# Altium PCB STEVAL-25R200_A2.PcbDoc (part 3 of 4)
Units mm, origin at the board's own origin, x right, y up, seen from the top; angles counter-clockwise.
Board outline 84.5 x 100 mm, 4 copper layers (Top Layer, F2, F3, Bottom Layer), stack 0.78 mm thick; 272 components, 152 nets, 679 pads, 380 vias.
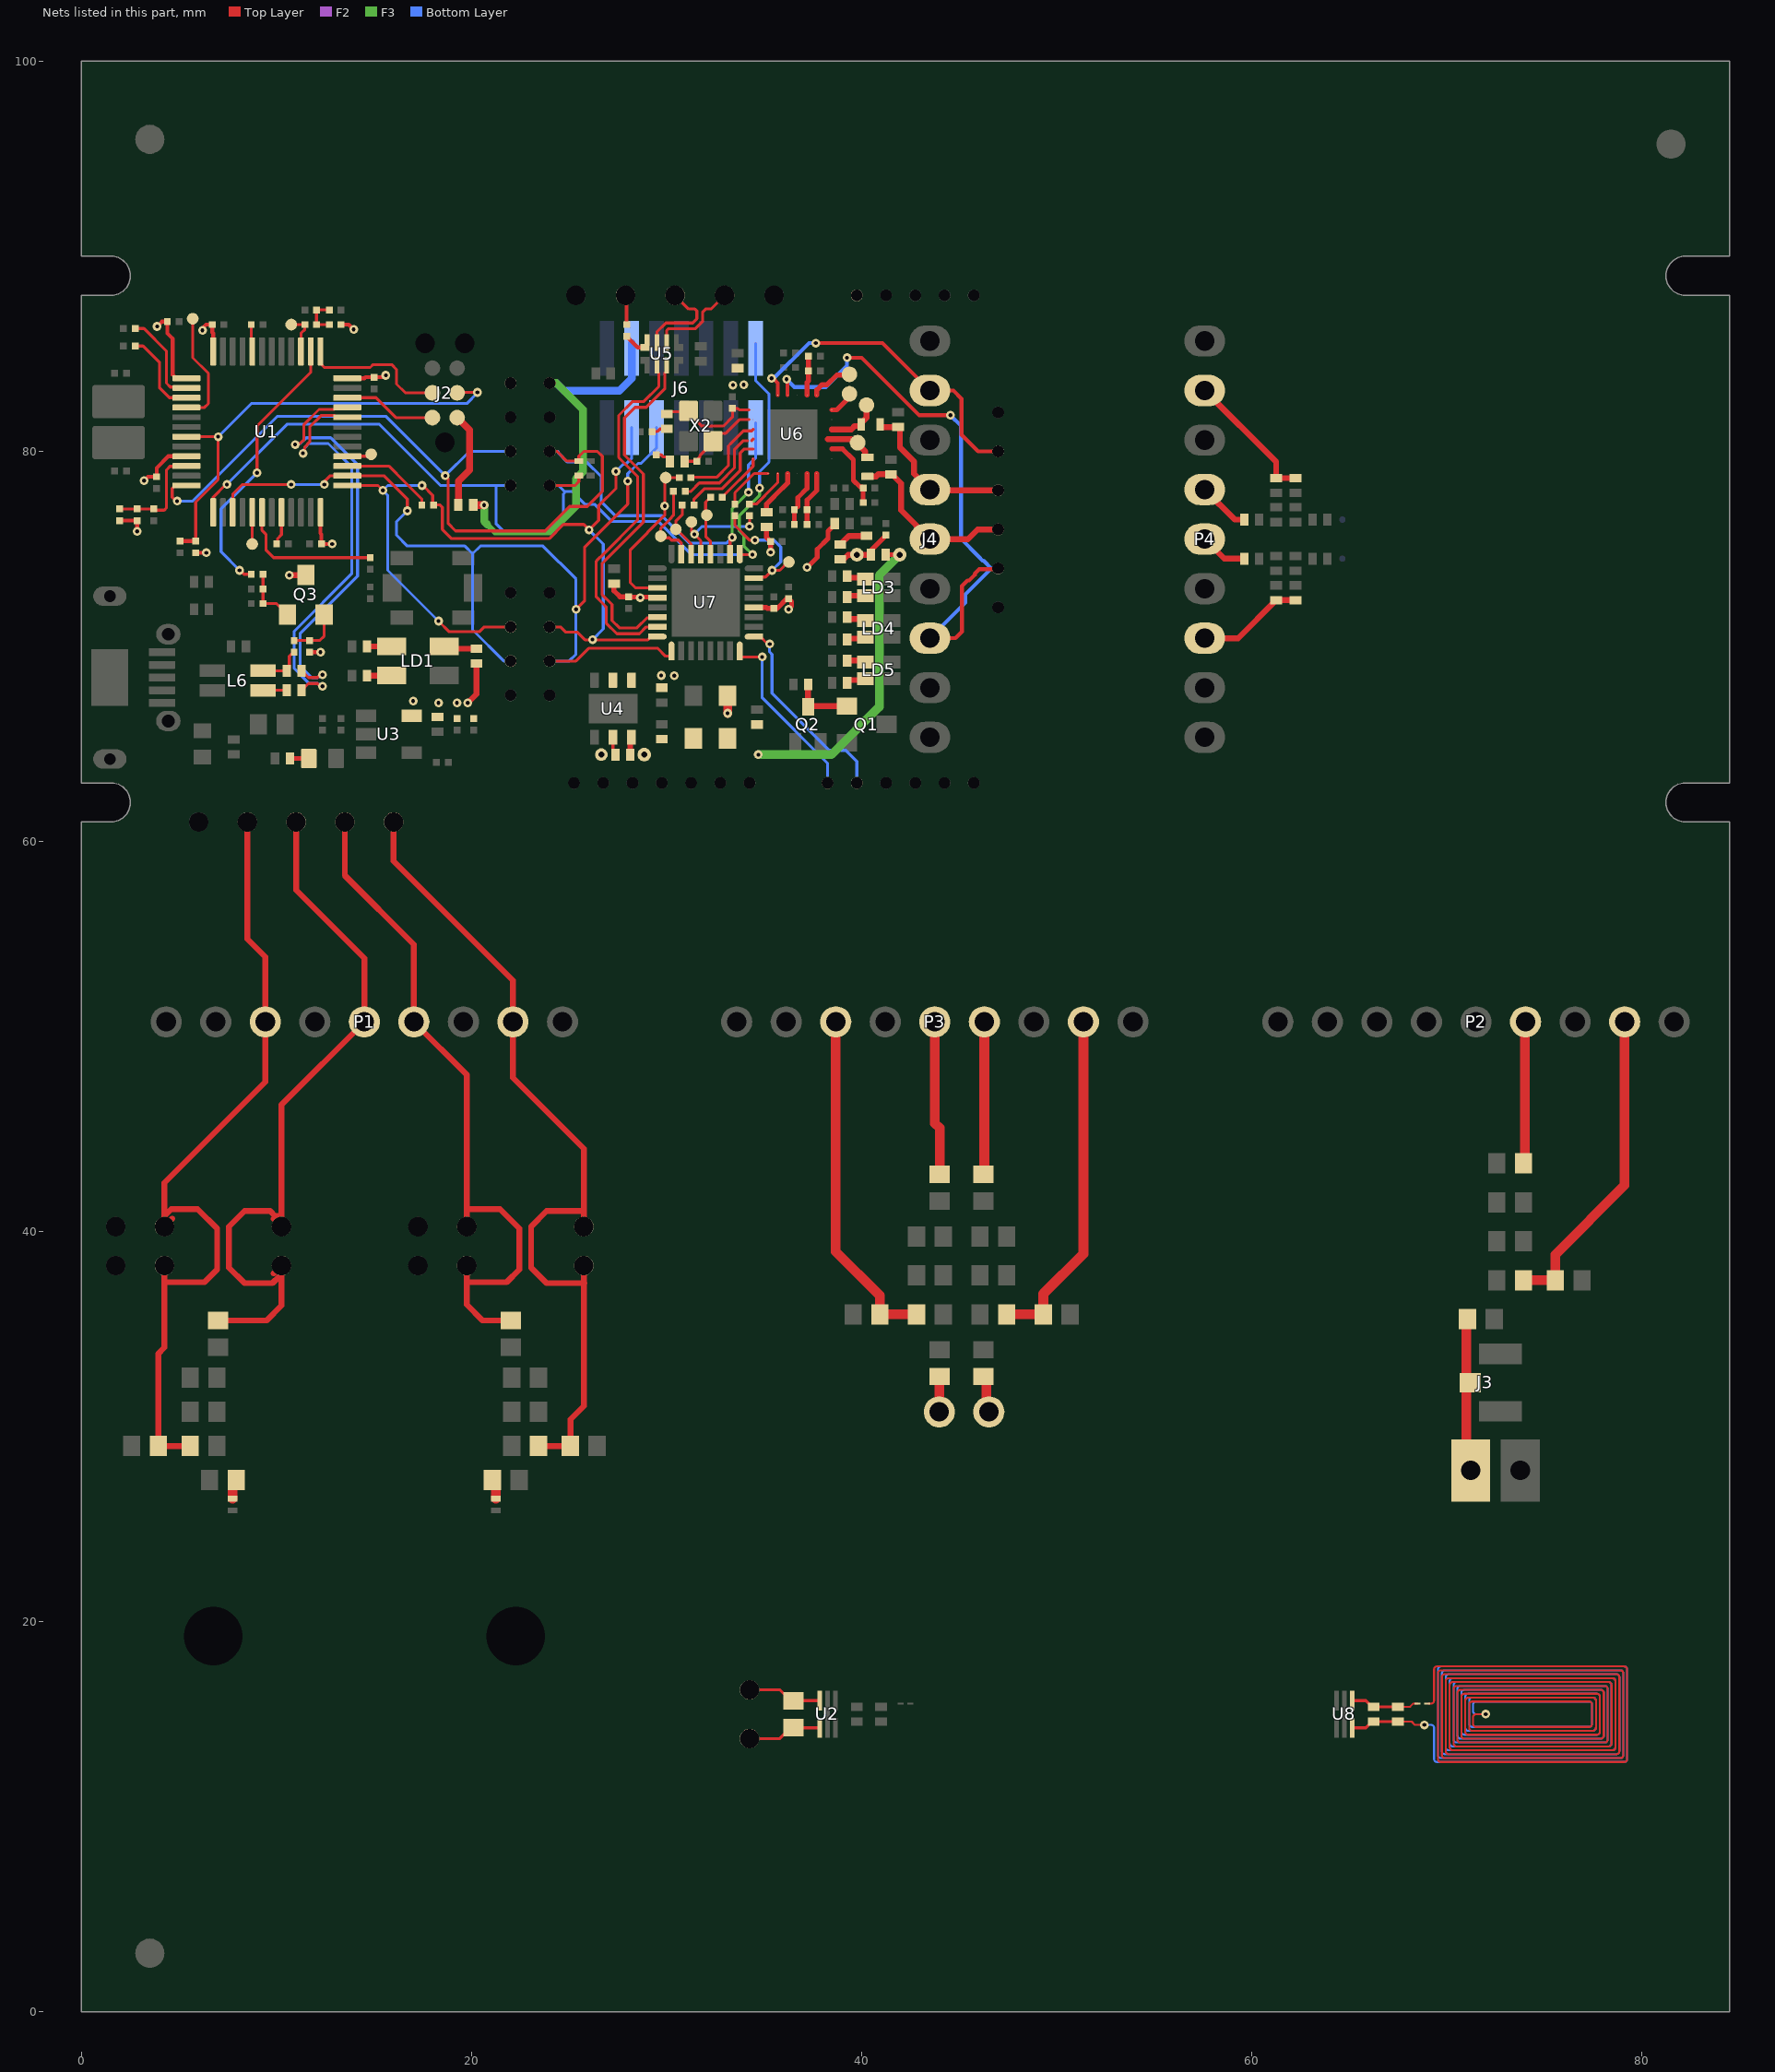
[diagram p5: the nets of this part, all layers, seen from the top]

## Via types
v1: diameter 0.45, hole 0.2, Top Layer to Bottom Layer, 380 vias

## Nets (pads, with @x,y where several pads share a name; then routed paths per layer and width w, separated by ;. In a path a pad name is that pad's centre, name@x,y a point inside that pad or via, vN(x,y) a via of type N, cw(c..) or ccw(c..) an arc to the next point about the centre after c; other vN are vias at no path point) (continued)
NetC78_1: C78.1 NT_TAG2.1 R57.1 U8.4 | length 3.5
  Top Layer w0.1: R57.1@67.5,15.631 68.121,15.631 68.29,15.8 NT_TAG2.1@68.5,15.8
  Top Layer w0.15: U8.4@65.15,15.95 65.85,15.95 C78.1@66.169,15.631 ; C78.1@66.25,15.631 R57.1@67.5,15.631
NetC78_2: C78.2 NT_TAG2.2 R57.2 U8.3 | length 443.5
  Top Layer w0.1: R57.2@67.5,14.869 68.201,14.869 68.37,14.7 v1(68.85,14.7) ; NT_TAG2.2@69.05,15.8 69.2,15.8 ccw(c69.2,15.95) 69.35,15.95 69.35,17.55 cw(c69.5,17.55) 69.5,17.7 79.1,17.7 cw(c79.1,17.55) 79.25,17.55 79.25,12.95 cw(c79.1,12.95) 79.1,12.8 69.7,12.8 cw(c69.7,12.95) 69.55,12.95 69.55,17.35 cw(c69.7,17.35) 69.7,17.5 ; 69.7,17.5 78.9,17.5 cw(c78.9,17.35) 79.05,17.35 79.05,13.15 ; v1(72,15.25) 71.5,15.25 ccw(c71.5,15.1) 71.35,15.1 71.35,14.75 ccw(c71.5,14.75) 71.5,14.6 77.3,14.6 ccw(c77.3,14.75) 77.45,14.75 77.45,15.75 ccw(c77.3,15.75) 77.3,15.9 71.3,15.9 ccw(c71.3,15.75) 71.15,15.75 71.15,14.55 ccw(c71.3,14.55) 71.3,14.4 77.5,14.4 ccw(c77.5,14.55) 77.65,14.55 77.65,15.95 ccw(c77.5,15.95) 77.5,16.1 71.1,16.1 ccw(c71.1,15.95) 70.95,15.95 70.95,14.35 ccw(c71.1,14.35) 71.1,14.2 77.7,14.2 ccw(c77.7,14.35) 77.85,14.35 77.85,16.15 ccw(c77.7,16.15) 77.7,16.3 70.9,16.3 ccw(c70.9,16.15) 70.75,16.15 70.75,14.15 ccw(c70.9,14.15) 70.9,14 77.9,14 ccw(c77.9,14.15) 78.05,14.15 78.05,16.35 ccw(c77.9,16.35) 77.9,16.5 70.7,16.5 ccw(c70.7,16.35) 70.55,16.35 70.55,13.95 ccw(c70.7,13.95) 70.7,13.8 78.1,13.8 ccw(c78.1,13.95) 78.25,13.95 78.25,16.55 ccw(c78.1,16.55) 78.1,16.7 ; 78.1,16.7 70.5,16.7 ccw(c70.5,16.55) 70.35,16.55 70.35,13.75 ccw(c70.5,13.75) 70.5,13.6 78.3,13.6 ccw(c78.3,13.75) 78.45,13.75 78.45,16.75 ccw(c78.3,16.75) 78.3,16.9 70.3,16.9 ccw(c70.3,16.75) 70.15,16.75 70.15,13.55 ccw(c70.3,13.55) 70.3,13.4 78.5,13.4 ccw(c78.5,13.55) 78.65,13.55 78.65,16.95 ccw(c78.5,16.95) 78.5,17.1 70.1,17.1 ccw(c70.1,16.95) 69.95,16.95 69.95,13.35 ccw(c70.1,13.35) 70.1,13.2 78.7,13.2 ccw(c78.7,13.35) 78.85,13.35 78.85,17.15 ccw(c78.7,17.15) 78.7,17.3 69.9,17.3 ccw(c69.9,17.15) 69.75,17.15 69.75,13.15 ccw(c69.9,13.15) 69.9,13 78.9,13 ccw(c78.9,13.15) 79.05,13.15
  Top Layer w0.15: U8.3@65.15,14.55 65.85,14.55 66.169,14.869 C78.2@66.25,14.869 R57.2@67.5,14.869
  Bottom Layer w0.1: v1(68.85,14.7) 69.2,14.7 cw(c69.2,14.55) 69.35,14.55 69.35,12.95 ccw(c69.5,12.95) 69.5,12.8 79.1,12.8 ccw(c79.1,12.95) 79.25,12.95 79.25,17.55 ccw(c79.1,17.55) 79.1,17.7 69.7,17.7 ccw(c69.7,17.55) 69.55,17.55 69.55,13.15 ccw(c69.7,13.15) 69.7,13 78.9,13 ccw(c78.9,13.15) 79.05,13.15 ; 69.9,17.5 78.9,17.5 cw(c78.9,17.35) 79.05,17.35 79.05,13.15 ; 69.9,17.5 ccw(c69.9,17.35) 69.75,17.35 69.75,13.35 ccw(c69.9,13.35) 69.9,13.2 78.7,13.2 ccw(c78.7,13.35) 78.85,13.35 78.85,17.15 ccw(c78.7,17.15) 78.7,17.3 70.1,17.3 ccw(c70.1,17.15) 69.95,17.15 69.95,13.55 ccw(c70.1,13.55) 70.1,13.4 78.5,13.4 ccw(c78.5,13.55) 78.65,13.55 78.65,16.95 ccw(c78.5,16.95) 78.5,17.1 70.3,17.1 ccw(c70.3,16.95) 70.15,16.95 70.15,13.75 ccw(c70.3,13.75) 70.3,13.6 78.3,13.6 ccw(c78.3,13.75) 78.45,13.75 78.45,16.75 ccw(c78.3,16.75) 78.3,16.9 70.5,16.9 ccw(c70.5,16.75) 70.35,16.75 70.35,13.95 ccw(c70.5,13.95) 70.5,13.8 78.1,13.8 ccw(c78.1,13.95) 78.25,13.95 78.25,16.55 ccw(c78.1,16.55) 78.1,16.7 ; 70.55,16.55 cw(c70.7,16.55) 70.7,16.7 78.1,16.7 ; 70.55,16.55 70.55,14.15 ccw(c70.7,14.15) 70.7,14 77.9,14 ccw(c77.9,14.15) 78.05,14.15 78.05,16.35 ccw(c77.9,16.35) 77.9,16.5 70.9,16.5 ccw(c70.9,16.35) 70.75,16.35 70.75,14.35 ccw(c70.9,14.35) 70.9,14.2 77.7,14.2 ccw(c77.7,14.35) 77.85,14.35 77.85,16.15 ccw(c77.7,16.15) 77.7,16.3 71.1,16.3 ccw(c71.1,16.15) 70.95,16.15 70.95,14.55 ccw(c71.1,14.55) 71.1,14.4 77.5,14.4 ccw(c77.5,14.55) 77.65,14.55 77.65,15.95 ccw(c77.5,15.95) 77.5,16.1 71.3,16.1 ccw(c71.3,15.95) 71.15,15.95 71.15,14.75 ccw(c71.3,14.75) 71.3,14.6 77.3,14.6 ccw(c77.3,14.75) 77.45,14.75 77.45,15.75 ccw(c77.3,15.75) 77.3,15.9 71.5,15.9 ccw(c71.5,15.75) 71.35,15.75 71.35,15.4 ccw(c71.5,15.4) 71.5,15.25 v1(72,15.25)
NetC79_2: C79.2 L4.2 pad.3@39.756,74.7 R37.1 | length 3
  Top Layer w0.25: R37.1@40.469,74.7 40.469,74.919 C79.2@41.25,75.7
  Top Layer w0.3: L4.2@38.9,74.469 39.069,74.469 39.3,74.7 R37.1@40.469,74.7
NetC80_2: C80.2 SB2.1 | length 0.8
  Top Layer w0.15: C80.2@29.25,81.01 29.51,81.01 29.649,81.149 SB2.1@30.01,81.149
NetC81_1: C81.1 SB3.1 | length 0.9
  Top Layer w0.15: C81.1@29.47,79.82 29.72,79.82 29.83,79.71 30.018,79.71 30.159,79.569 SB3.1@30.159,79.48
NetJ2_1: J2.1 R50.1 | length 5
  Top Layer w0.35: J2.1@19.26,81.73 19.9,81.09 19.9,79.05 19.319,78.469 R50.1@19.319,77.25
NetJ3_1: J3.1 JP1.2 pad.5 R19.2 | length 8.9
  Top Layer w0.5: JP1.2@71,27 71,27.75 JP1.2@71,28 ; R19.2@71.064,35.5 71,35.436 71,32.399 JP1.2@71,28 ; JP1.2@71.25,27.75 JP1.2@71,28
NetJP2_1: JP2.1 R52.2 | length 1.8
  Top Layer w0.5: JP2.1@43.98,30.75 43.99,30.76 43.99,32.554 R52.2@44,32.564
NetJP2_2: JP2.2 R51.2 | length 1.9
  Top Layer w0.5: R51.2@46.25,32.564 46.385,32.429 46.385,30.885 JP2.2@46.52,30.75
NetL4_1: L4.1 R59.2 | length 1.5
  Top Layer w0.3: L4.1@38.9,75.231 39.338,75.669 R59.2@40.25,75.669
NetL6_2: L6.2 R2.1 R8.1 | length 2.4
  Top Layer w0.15: L6.2@9.3,68.75 R2.1@10.519,68.75 10.65,68.881 10.65,69.5 10.85,69.7 R8.1@10.9,69.7
NetL6_3: L6.3 R1.1 | length 1.2
  Top Layer w0.15: L6.3@9.3,67.75 R1.1@10.519,67.75
NetLD1_A1: LD1.A1 R43.1 | length 1.3
  Top Layer w0.3: R43.1@14.631,68.5 LD1.A1@15.9,68.5
NetLD1_A2: LD1.A2 R56.1 | length 1.7
  Top Layer w0.3: LD1.A2@18.6,70 18.719,69.881 R56.1@20.25,69.881
NetLD1_K2: LD1.K2 R44.1 | length 1.3
  Top Layer w0.3: R44.1@14.631,70 LD1.K2@15.9,70
NetLD2_A: LD2.A R12.1 | length 1
  Top Layer w0.25: R12.1@10.681,64.25 LD2.A@11.65,64.25
NetLD3_A1: LD3.A1 R21.1 | length 1
  Top Layer w0.3: R21.1@39.256,72.525 39.331,72.6 LD3.A1@40.2,72.6
NetLD3_A2: LD3.A2 R22.1 | length 1
  Top Layer w0.3: R22.1@39.256,73.525 40.125,73.525 LD3.A2@40.2,73.45
NetLD4_A1: LD4.A1 R23.1 | length 1
  Top Layer w0.3: R23.1@39.256,70.4 40.125,70.4 LD4.A1@40.2,70.475
NetLD4_A2: LD4.A2 R24.1 | length 1
  Top Layer w0.3: R24.1@39.256,71.4 40.125,71.4 LD4.A2@40.2,71.325
NetLD5_A1: LD5.A1 R25.1 | length 1
  Top Layer w0.3: R25.1@39.256,68.275 40.125,68.275 LD5.A1@40.2,68.35
NetLD5_A2: LD5.A2 R26.1 | length 1
  Top Layer w0.3: R26.1@39.256,69.275 40.125,69.275 LD5.A2@40.2,69.2
NetNT_C7_1_2: NT_C7_1.2 R17.2 | length 1
  Top Layer w0.5: NT_C7_1.2@7.75,26.3 7.75,27.064 R17.2@7.936,27.25
NetNT_C7_2_2: NT_C7_2.2 R16.2 | length 1
  Top Layer w0.5: R16.2@21.064,27.25 21.25,27.064 NT_C7_2.2@21.25,26.3
NetQ1_G: Q1.G Q2.C R20.1 | length 3.2
  Top Layer w0.3: R20.1@37.261,68.05 37.25,68.039 Q2.C@37.25,66.9 37.29,66.94 Q1.G@39.234,66.94
NetQ3_B: Q3.B R3.1 R5.1 R7.2 | length 3
  Top Layer w0.15: R5.1@9.3,73.7 R7.2@9.3,72.95 R3.1@9.3,72.2 9.994,72.2 Q3.B@10.56,71.634
NetQ3_E: Q3.E R6.1 R8.2 | length 2.7
  Top Layer w0.15: R8.2@10.9,70.3 R6.1@11.7,70.3 12.2,70.3 12.44,70.54 Q3.E@12.44,71.634
NetR9_2: R9.2 R10.1 R11.2 R40.2 | length 2.1
  Top Layer w0.15: R11.2@12.7,86.5 R40.2@12.05,86.5 R10.1@12.05,87.25 R9.2@12.7,87.25
NetR15_2: R15.2 U5.4 | length 1.2
  Top Layer w0.2: R15.2@27.95,85.9 28.525,85.325 U5.4@28.887,85.325
NetR29_2: R29.2 U6.21 | length 4.8
  Top Layer w0.15: R29.2@31.25,78.65 31.28,78.68 32.58,78.68 33.17,79.27 33.17,80.281 33.3,80.411 33.939,81.05 34.362,81.05 U6.21@34.437,81.125
NetR30_2: R30.2 U6.22 | length 5
  Top Layer w0.15: R30.2@30.95,77.95 31.254,77.95 31.675,78.371 31.675,78.38 31.705,78.38 32.704,78.38 33.47,79.146 33.47,80.087 33.6,80.217 33.933,80.55 34.162,80.55 ; 34.362,80.55 U6.22@34.437,80.625
NetR31_2: R31.2 U6.23 | length 4.9
  Top Layer w0.15: R31.2@31.4,77.25 31.4,77.55 31.93,78.08 32.829,78.08 33.77,79.021 33.77,79.912 33.983,80.125 U6.23@34.437,80.125
NetR32_2: R32.2 U6.24 | length 2.6
  Top Layer w0.15: R32.2@32.85,77.65 32.98,77.78 34.437,79.237 U6.24@34.437,79.625
NetR33_2: R33.2 U6.1 | length 2.7
  Top Layer w0.15: R33.2@33.5,77.3 33.5,77.876 34.486,78.862 U6.1@35.2,78.862
NetR34_2: R34.2 U6.2 | length 2.4
  Top Layer w0.15: R34.2@34.25,77.3 34.6,77.3 35.5,78.2 35.7,78.4 U6.2@35.7,78.862
NetR35_2: R35.2 U6.3 | length 2.4
  Top Layer w0.25: R35.2@35.125,76.881 35.125,77.305 35.969,78.149 35.974,78.149 36.15,78.325 36.15,78.33 36.2,78.38 U6.3@36.2,78.862
NetR38_1: R38.1 R39.1 R41.2 U1.10 | length 5.5
  Top Layer w0.15: R39.1@1.95,77.05 R41.2@3.7,77.05 3.762,76.988 4.238,76.988 4.35,77.1 4.35,79.05 4.529,79.229 5.354,79.229 U1.10@5.375,79.25
NetR46_2: R46.2 U1.44 | length 1.4
  Top Layer w0.15: R46.2@8.7,86.5 8.7,85.175 U1.44@8.75,85.125
NetR47_2: R47.2 U1.3 | length 4.5
  Top Layer w0.15: R47.2@2.75,85.4 3.15,85.4 4,84.55 4,83.25 4.5,82.75 U1.3@5.375,82.75
NetR48_2: R48.2 U1.2 | length 4.9
  Top Layer w0.15: R48.2@2.75,86.3 3.2,86.3 4.35,85.15 4.35,83.5 4.554,83.296 5.329,83.296 U1.2@5.375,83.25
NetR49_2: R49.2 U1.20 | length 1.7
  Top Layer w0.15: R49.2@10,75.25 10.05,75.3 10.05,75.525 10.25,75.725 U1.20@10.25,76.875
NetR58_1: pad.1 R58.1 U4.2 | length 0.9
  Top Layer w0.15: U4.2@27.25,65.342 27.25,64.569 R58.1@27.369,64.45
NetSB1_1: SB1.1 U2.5 V62.1 | length 3.8
  Top Layer w0.15: V62.1@34.25,16.5 35.81,16.5 36.374,15.936 SB1.1@36.5,15.936 36.514,15.95 U2.5@37.85,15.95
NetSB1_2: SB1.2 U2.1 V61.1 | length 3.8
  Top Layer w0.15: V61.1@34.25,14 35.81,14 36.374,14.564 SB1.2@36.5,14.564 36.514,14.55 U2.1@37.85,14.55
NetTP6_1: TP6.1 U1.17 | length 1.6
  Top Layer w0.15: TP6.1@8.75,75.25 U1.17@8.75,76.875
NetTP7_1: TP7.1 U1.28 | length 1.3
  Top Layer w0.15: U1.28@13.625,79.75 14.75,79.75 TP7.1@14.85,79.85
NetTP8_1: TP8.1 U1.4 | length 5.9
  Top Layer w0.15: U1.4@5.375,82.25 6.3,82.25 6.5,82.45 6.5,84 5.7,84.8 TP8.1@5.7,86.8
PWR_EXT: R40.1 TP3.1 U1.39 | length 2.2
  Top Layer w0.15: TP3.1@10.75,86.5 R40.1@11.45,86.5 11.45,86.25 11.25,86.05 U1.39@11.25,85.125
RFI1_25R200: J4.7 U6.16 V13.1 | length 31.9
  Top Layer w0.2: v1(36.15,83.7) 36.2,83.65 U6.16@36.2,82.888 ; v1(39.25,84.8) 40,84.8 42.95,81.85 v1(44.55,81.85) ; J4.7@43.5,70.42 44.81,70.42 45.14,70.75 45.14,73.09 45.426,73.376 45.514,73.376 45.8,73.661 45.8,73.726 46.034,73.96 46.1,73.96 47,73.96 V13.1@47,74
  Bottom Layer w0.2: v1(36.15,83.7) 36.55,83.3 38.15,83.3 39.25,84.4 v1(39.25,84.8) ; J4.7@43.5,70.42 45.32,72.24 45.32,72.67 46.1,73.45 46.65,74 ; v1(44.55,81.85) 45.1,81.3 45.1,75.5 46,74.6 46.2,74.4 46.25,74.4 46.65,74 ; V13.1@47,74 46.65,74
RFI1_C6_ANT: C64.1 C65.2 P4.7 | length 5.5
  Top Layer w0.3: P4.7@57.59,70.42 59.301,70.42 C65.2@61.25,72.369 C64.1@62.25,72.369
RFI1_C7_ANT: C26.1 C27.2 P1.7 V18.1 V52.1 V54.1 | length 43.3
  Top Layer w0.3: V18.1@4.15,40.17 V18.1@4.25,40.27 ; V52.1@4.25,38.25 4.25,37.45 ; V18.1@4.25,40.25 V18.1@4.25,40.27 ; 4.25,40.8 4.6,41.15 5.95,41.15 6.95,40.15 6.95,38.05 6.3,37.4 4.3,37.4 4.25,37.45 ; 4.64,40.66 V18.1@4.25,40.27 ; C26.1@5.564,29 C27.2@3.936,29 3.936,33.736 4.25,34.05 4.25,37.45 ; V54.1@8.5,61 8.5,55 9.42,54.08 P1.7@9.42,50.75 9.42,47.67 4.25,42.5 V18.1@4.25,40.27
RFI1_Flex_ANT: C75.1 C76.2 P3.7 | length 17.8
  Top Layer w0.5: P3.7@38.67,50.75 38.67,38.98 40.936,36.714 C76.2@40.936,35.75 C75.1@42.814,35.75
RFI2_25R200: J4.2 U6.17 V14.1 | length 16.8
  Top Layer w0.2: v1(35.375,83.75) 35.45,83.75 35.7,83.5 U6.17@35.7,82.888 ; v1(37.65,85.55) 41.07,85.55 J4.2@43.5,83.12 44.7,83.12 45.12,82.7 45.12,80.85 45.97,80 V14.1@47,80
  Bottom Layer w0.2: v1(35.375,83.75) 35.5,83.75 37.3,85.55 v1(37.65,85.55)
RFI2_50R: C28.1 C29.2 P2.2 | length 16.4
  Top Layer w0.5: C29.2@73.936,37.5 C28.1@75.564,37.5 75.564,38.814 79.12,42.37 P2.2@79.12,50.75
RFI2_C6_ANT: C54.1 C55.2 P4.2 | length 7
  Top Layer w0.3: P4.2@57.59,83.12 61.25,79.46 C54.1@61.25,78.631 C55.2@62.25,78.631
RFI2_C7_ANT: C13.1 C14.2 P1.2 V47.1 V53.1 V59.1 | length 44.2
  Top Layer w0.3: V59.1@16,61 16,59 22.12,52.88 P1.2@22.12,50.75 22.12,47.88 25.75,44.25 25.75,41.05 ; C14.2@23.436,29 C13.1@25.064,29 25.064,30.364 25.75,31.05 25.75,37.35 ; V53.1@25.75,38.25 25.75,37.35 ; V47.1@25.75,40.25 25.75,41.05 ; 25.77,41.05 25.75,41.05 ; 25.78,37.35 25.75,37.35 ; 25.75,37.35 23.85,37.35 23.05,38.15 23.05,40.25 23.85,41.05 25.75,41.05
RFI2_Flex_ANT: C67.1 C68.2 P3.2 | length 17.7
  Top Layer w0.5: C68.2@47.436,35.75 C67.1@49.314,35.75 49.314,36.807 51.37,38.862 P3.2@51.37,50.75
RFO1_25R200: L2.1 TP5.1 U6.9 | length 2.5
  Top Layer w0.3: 38.263,80.625 39.477,80.625 39.657,80.445 TP5.1@39.792,80.445 39.792,80.375 40.17,79.997 L2.1@40.17,79.697
RFO1_C6_ANT: C63.1 P4.5 | length 2.4
  Top Layer w0.3: P4.5@57.59,75.5 58.59,74.5 C63.1@59.619,74.5
RFO1_C7_ANT: C25.1 P1.5 V5.1 V49.1 V51.1 | length 39.1
  Top Layer w0.3: C25.1@7,35.436 9.486,35.436 10.25,36.2 V49.1@10.25,38.25 9.85,37.85 ; 9.85,40.65 V5.1@10.25,40.25 10.25,40.8 ; 10.25,37.7 10.14,37.7 9.79,37.35 8.922,37.35 8.35,37.35 7.55,38.15 7.55,40.25 8.35,41.05 9.67,41.05 9.92,40.8 10.25,40.8 ; V51.1@11,61 11,57.5 14.5,54 P1.5@14.5,50.75 10.25,46.5 10.25,40.8
RFO1_Cast: C60.1 J4.5 L2.2 V11.1 | length 9.1
  Top Layer w0.3: L2.2@40.3,78.712 40.743,78.712 40.854,78.823 C60.1@41.496,78.823 ; C60.1@41.5,78.869 42.02,78.349 42.02,76.98 J4.5@43.5,75.5 45.45,75.5 45.95,76 V11.1@47,76
RFO1_Flex_ANT: C74.1 P3.5 | length 7.9
  Top Layer w0.5: P3.5@43.75,50.75 43.75,45.55 44,45.3 C74.1@44,42.936
RFO2_25R200: L1.1 TP4.1 U6.10 | length 2.8
  Top Layer w0.3: U6.10@38.463,81.125 39.465,81.125 39.64,81.3 39.935,81.3 39.973,81.338 39.973,81.487 40.01,81.525 40.05,81.525 40.25,81.725 TP4.1@40.25,82.375
RFO2_50R: C30.1 P2.4 | length 7.3
  Top Layer w0.5: C30.1@73.936,43.5 74,43.564 74,50.75 P2.4@74.04,50.75
RFO2_C6_ANT: C56.1 P4.4 | length 2.7
  Top Layer w0.3: P4.4@57.59,78.04 59.13,76.5 C56.1@59.619,76.5
RFO2_C7_ANT: C16.1 P1.4 V41.1 V50.1 V58.1 | length 36.1
  Top Layer w0.3: V58.1@13.5,61 13.5,58.25 17.04,54.71 P1.4@17.04,50.75 19.75,48.04 19.75,41.15 ; 19.74,41.15 19.75,41.15 ; V50.1@19.75,38.25 19.75,37.45 ; V41.1@19.75,40.25 19.75,41.15 ; C16.1@22,35.436 20.564,35.436 19.75,36.25 19.75,37.45 ; 19.75,37.45 19.8,37.4 21.8,37.4 22.45,38.05 22.45,40.15 21.45,41.15 19.75,41.15
RFO2_Cast: C57.2 J4.4 L1.2 V12.1 | length 8.9
  Top Layer w0.3: L1.2@40.948,81.379 40.938,81.369 40.938,81.247 41.72,81.247 C57.2@41.723,81.244 ; C57.2@41.961,81.247 41.961,80.198 42.68,79.479 42.68,78.86 J4.4@43.5,78.04 43.54,78 46.55,78 V12.1@47,78 ; C57.2@41.723,81.244 C57.2@41.875,81.244 ; C57.2@41.723,81.244 C57.2@41.875,81.244 ; C57.2@41.723,81.244 C57.2@41.875,81.244 ; C57.2@41.723,81.244 C57.2@41.875,81.244
RFO2_Flex_ANT: C69.1 P3.4 | length 7.8
  Top Layer w0.5: C69.1@46.25,42.936 46.29,42.976 P3.4@46.29,50.75
SPI1_MISO: R34.1 TP17.1 U7.13 | length 5.5
  Top Layer w0.15: TP17.1@31.27,76.38 31.27,75.9 v1(31.42,75.75) 31.75,75.42 U7.13@31.75,74.725 ; v1(34.24,76.15) 34.24,76.26 34.25,76.27 R34.1@34.25,76.7
  Bottom Layer w0.15: v1@31.325,75.655 v1(31.42,75.75) 31.82,76.15 v1(34.24,76.15)
SPI1_MOSI: R31.1 TP16.1 U7.14 | length 3.2
  Top Layer w0.15: R31.1@30.8,77.25 30.8,76.75 30.47,76.42 TP16.1@30.47,76 30.52,76 31.25,75.27 31.25,74.852 U7.14@31.25,74.725 31.2,74.775 U7.14@31.2,74.852
SPI1_NSS: R30.1 TP15.1 U7.15 | length 4.3
  Top Layer w0.15: R30.1@30.35,77.95 30.35,76.724 30.17,76.544 30.17,76.526 29.7,76.056 TP15.1@29.7,75.65 29.786,75.564 30.128,75.564 30.242,75.45 30.61,75.45 30.75,75.31 U7.15@30.75,74.725
SPI1_SCK: R32.1 TP19.1 U7.12 | length 3.2
  Top Layer w0.15: U7.12@32.25,74.725 32.25,75.38 32.015,75.615 32.015,76.685 TP19.1@32.06,76.73 32,76.79 32,77.4 R32.1@32.25,77.65
ST25R_IRQ: R33.1 TP18.1 U7.7 | length 6.8
  Top Layer w0.15: R33.1@33.5,76.7 33.5,76.2 34.25,75.45 v1(34.528,75.45) ; U7.7@34.475,73.5 34.529,73.554 35.064,73.554 v1(35.41,73.9) 35.8,73.9 36.23,74.33 TP18.1@36.27,74.33
  Bottom Layer w0.15: v1(34.528,75.45) 35.5,75.45 35.85,75.1 35.85,74.34 v1(35.41,73.9)
ST25R_RST: R29.1 TP14.1 U7.19 | length 8.3
  Top Layer w0.15: U7.19@29.525,73 28.4,73 28.14,73.26 28.14,74.96 29.9,76.72 v1(29.9,77.2) 29.9,78.6 TP14.1@29.95,78.65 R29.1@30.65,78.65
STL_USB_D_N: R1.2 U1.32 | length 21.7
  Top Layer w0.15: R1.2@11.281,67.75 11.631,68.1 12.093,68.1 12.243,67.95 v1(12.35,67.95) ; v1(11.35,79.9) 11.35,80.043 11.45,80.143 11.45,80.226 11.7,80.476 11.7,81.25 12.3,81.85 12.95,81.85 13.05,81.75 U1.32@13.625,81.75
  Bottom Layer w0.15: v1(11.35,79.9) 11.279,79.971 11.45,80.143 11.45,80.2 11.65,80.4 12.65,80.4 13.85,79.2 13.85,73.724 10.9,70.774 10.9,68.876 11.676,68.1 12.093,68.1 12.143,68.05 12.25,68.05 v1(12.35,67.95)
STL_USB_D_P: R2.2 U1.33 | length 22.1
  Top Layer w0.15: v1(10.95,80.35) 11.093,80.35 11.143,80.4 11.2,80.4 11.4,80.6 11.4,81.374 12.176,82.15 12.95,82.15 13.05,82.25 U1.33@13.625,82.25 ; R2.2@11.281,68.75 11.631,68.4 12.093,68.4 12.243,68.55 v1(12.35,68.55)
  Bottom Layer w0.15: v1(10.95,80.35) 11,80.4 11.226,80.4 11.526,80.7 12.774,80.7 14.15,79.324 14.15,73.6 11.2,70.65 11.2,69 11.8,68.4 12.093,68.4 12.143,68.45 12.25,68.45 v1(12.35,68.55)
STM_JTCK: J2.4 U1.37 | length 7.5
  Top Layer w0.15: U1.37@12.25,85.125 12.25,84.5 12.45,84.3 14.8,84.3 14.95,84.45 15.9,84.45 16.15,84.2 16.15,83.45 16.6,83 J2.4@17.99,83
STM_JTMS_SWDIO: J2.2 U1.34 | length 4.8
  Top Layer w0.15: U1.34@13.625,82.75 15.1,82.75 16.12,81.73 J2.2@17.99,81.73
STM_RST: C10.1 J2.3 R45.1 U1.7 | length 23.6
  Top Layer w0.15: U1.7@5.375,80.75 v1(7,80.75) 7,78.55 5.85,77.4 R45.1@5.85,75.4 ; J2.3@19.26,83 19.285,83.025 v1(20.3,83.025)
  Top Layer w0.2: C10.1@5.05,75.4 R45.1@5.85,75.4
  Bottom Layer w0.15: v1(7,80.75) 8.7,82.45 19.75,82.45 20.3,83 v1(20.3,83.025)
T_JTCK: J6.6 U1.15 U1.26 U7.25 V4.1 V39.1 | length 53.3
  Top Layer w0.15: U1.15@7.75,76.875 7.75,77.8 8.25,78.3 v1(10.75,78.3) ; v1(12.45,78.3) 12.45,78.45 12.75,78.75 U1.26@13.625,78.75 15.5,78.75 16.25,78 16.7,77.55 v1(16.7,76.95) ; V4.1@24,69.25 25.35,69.25 26,69.9 28.224,69.9 29.55,69.9 29.95,69.5 30.25,69.5 U7.25@30.25,69.775 ; v1(25.35,71.9) 25.8,72.35 25.8,75.1 28,77.3 v1(28,78.47)
  Bottom Layer w0.15: v1(10.75,78.3) v1(12.45,78.3) ; v1(16.7,76.95) 16.15,76.4 16.15,75.7 16.7,75.15 19.65,75.15 20.05,74.75 ; V39.1@22,69.25 21.65,69.25 20.05,70.85 20.05,74.75 ; V4.1@24,69.25 25,69.25 25.35,69.6 v1(25.35,71.9) 25.35,73.459 23.659,75.15 20.45,75.15 20.05,74.75 ; v1(28,78.47) 28,78.85 28.534,79.384 28.694,79.384 29.48,80.17 J6.6@29.48,81.215
T_JTMS: R55.2 U1.27 | length 4.8
  Top Layer w0.15: U1.27@13.625,79.25 15.75,79.25 16.575,78.425 17.45,77.55 R55.2@17.45,77.25
T_NRST: R54.2 U1.18 | length 7.5
  Top Layer w0.15: U1.18@9.25,76.875 9.25,75.95 9.45,75.75 9.45,74.95 9.85,74.55 R54.2@14.8,74.55
T_SWDIO_IN: J6.4 R55.1 U1.25 U7.24 V3.1 V42.1 | length 45.2
  Top Layer w0.15: U1.25@13.625,78.25 15.2,78.25 v1(15.45,78) ; v1(17.45,78.25) 17.5,78.25 18,77.75 18,77.3 R55.1@18.05,77.25 18.379,77.25 18.5,77.129 18.5,76 18.975,75.525 23.975,75.525 24.7,76.25 25.75,76.25 v1(26.025,75.975) 26.514,76.464 26.514,77.214 27.4,78.1 v1(27.4,78.97) ; v1(18.3,71.3) 18.85,70.75 20.4,70.75 20.65,71 V42.1@22,71 ; V3.1@24,71 24.55,71 24.81,70.74 25.41,70.74 25.813,70.337 29.037,70.337 U7.24@29.2,70.5 U7.24@29.525,70.5
  Bottom Layer w0.15: v1(17.45,78.25) 15.7,78.25 v1(15.45,78) 15.7,77.75 15.7,73.9 v1(18.3,71.3) ; v1(26.025,75.975) 26.75,75.25 26.75,70.9 v1(26.2,70.35) ; v1(27.4,78.97) 27.78,79.35 27.91,79.35 28.21,79.65 J6.4@28.21,81.215
TAD1_200: TP1.1 U6.13 | length 2.3
  Top Layer w0.25: U6.13@37.7,82.888 37.7,83.15 37.969,83.419 38.231,83.419 38.725,83.913 39.338,83.913 TP1.1@39.375,83.95
TAD2_200: TP2.1 U6.12 | length 1.6
  Top Layer w0.25: U6.12@38.463,82.125 38.725,82.125 ; 38.525,82.125 38.726,82.125 39.27,82.669 39.27,82.845 TP2.1@39.375,82.95
UART6_RX: U7.1 V28.1 | length 10.4
  Top Layer w0.15: U7.1@34.475,70.5 U7.1@34.8,70.5 35.18,70.12 v1(35.28,70.12)
  Bottom Layer w0.15: v1(35.28,70.12) 35.28,69.716 35.405,69.591 35.405,67.595 38.33,64.67 39.19,64.67 39.75,64.11 39.75,63.45 V28.1@39.75,63
UART6_TX: U7.32 V27.1 | length 9.3
  Top Layer w0.15: U7.32@33.75,69.45 33.76,69.46 v1(34.9,69.46) ; U7.32@33.75,69.5 U7.32@33.75,69.775
  Bottom Layer w0.15: v1(34.9,69.46) 34.9,67.36 38.25,64.01 V27.1@38.25,63
UART_RX: D7.K J6.14 U1.12 U7.10 V7.1 V43.1 | length 58.3
  Top Layer w0.15: v1(4.9,77.45) 4.85,77.45 4.65,77.65 4.65,78.1 4.8,78.25 U1.12@5.375,78.25 ; v1(18.65,78.75) 18.8,78.6 18.8,76.3 19.175,75.925 23.775,75.925 25.025,77.175 25.925,77.175 26.7,77.95 26.7,79.75 26.45,80 25.75,80 25.5,79.75 D7.K@25.5,79.5 24.89,79.5 24.39,80 V7.1@24,80 ; U7.10@33.25,74.725 33.25,75.48 v1(33.36,75.59)
  F3 w0.15: v1(33.36,75.59) 33.36,77.06 v1(34.2,77.9)
  Bottom Layer w0.15: v1(4.9,77.45) 5.7,77.45 10.05,81.8 15.6,81.8 v1(18.65,78.75) 19.9,80 V43.1@22,80 ; V7.1@24,80 24.45,80 24.45,79.911 24.911,79.45 25.9,79.45 26.65,78.7 26.65,77.413 27.363,76.7 29.76,76.7 31.173,75.287 33.057,75.287 v1(33.36,75.59) ; v1(34.2,77.9) 34.2,79.3 34.56,79.66 J6.14@34.56,81.215 J6.14@34.56,81.465
UART_TX: D6.K J6.13 U1.13 U7.9 V6.1 V44.1 | length 52.5
  Top Layer w0.15: U1.13@6.75,76.875 6.75,77.65 7.4,78.3 v1(7.45,78.3) ; V6.1@24,78.25 25.3,78.25 25.5,78.45 D6.K@25.5,78.75 ; U7.9@33.75,74.725 33.765,74.71 v1(34.4,74.71)
  F3 w0.15: v1(34.4,74.71) 33.96,75.15 33.96,75.68 33.72,75.92 33.72,76.71 34.76,77.75 v1(34.76,78.12)
  Bottom Layer w0.15: v1(7.45,78.3) 10.55,81.4 15.25,81.4 18.4,78.25 21.25,78.25 ; V44.1@22,78.25 21.25,78.25 ; V6.1@24,78.25 24.45,78.25 24.75,77.95 ; v1(34.4,74.71) 31.27,74.71 29.58,76.4 27.203,76.4 26.326,77.276 25.824,77.276 25.15,77.95 24.75,77.95 ; J6.13@34.56,85.535 J6.13@34.56,85.285 34.56,83.64 35.25,82.95 35.25,79.45 34.76,78.96 v1(34.76,78.12) ; 21.25,78.25 21.25,76.3 21.7,75.85 23.75,75.85 24.7,76.8 24.7,77.8 24.75,77.85 24.75,77.95
USB_ID: R15.1 V36.1 | length 1.5
  Top Layer w0.2: R15.1@27.95,86.5 V36.1@27.95,88
USB_IN_N: U5.2 V34.1 | length 4.6
  Top Layer w0.15: U5.2@30,85.575 30,86.2 30.082,86.282 31.457,86.282 31.85,86.676 31.85,87.15 32,87.3 32.27,87.3 V34.1@32.97,88
USB_IN_P: U5.3 V35.1 | length 4.7
  Top Layer w0.15: U5.3@29.5,85.575 29.5,86.124 29.958,86.582 31.332,86.582 31.55,86.8 31.55,87.2 31.45,87.3 31.13,87.3 V35.1@30.43,88
USB_N: U5.7 U7.22 | length 18.5
  Top Layer w0.15: U7.22@29.525,71.5 29.492,71.467 28.997,71.467 28.48,70.95 27.574,70.95 27.2,71.324 27.2,72.15 26.687,72.663 26.687,74.242 26.745,74.3 26.892,74.447 28.81,76.365 28.81,78.84 27.84,79.81 27.84,81.72 28.38,82.26 28.955,82.26 29.9,83.205 29.9,84.011 30,84.111 U5.7@30,84.425
USB_P: U5.6 U7.23 | length 18.9
  Top Layer w0.15: 26.713,72.213 26.387,72.539 26.387,74.366 26.445,74.424 26.767,74.747 28.51,76.489 28.51,78.716 27.54,79.686 27.54,81.844 28.256,82.56 28.83,82.56 29.6,83.33 29.6,84.008 29.5,84.108 U5.6@29.5,84.425 ; 26.763,72.163 26.9,72.026 26.9,71.2 27.45,70.65 28.605,70.65 28.955,71 U7.23@29.525,71
USB_RENUMn: R5.2 U1.38 | length 14.2
  Top Layer w0.15: v1(8.1,73.9) 8.138,73.9 8.338,73.7 R5.2@8.7,73.7 ; v1(9,78.9) 9,81.3 11.75,84.05 U1.38@11.75,85.125
  Bottom Layer w0.15: v1(8.1,73.9) 7.15,74.85 7.15,77.05 v1(9,78.9)
V_USB: D3.A R13.2 | length 0.9
  Top Layer w0.45: v1(33.125,66.571) D3.A@33.125,67.467
  other v1: 33.4,83.4 33.95,83.42
VCC_STLK: C2.1 C3.1 C4.2 C5.1 C6.1 C12.2 C15.2 C19.2 J6.3 Q3.C R6.2 R11.1 R38.2 R39.2 R45.2 R50.2 R56.2 U1.1 U1.9 U1.24 U1.36 U1.48 U3.5 V38.1 V46.1 | length 40.6
  Top Layer w0.2: R39.2@1.95,76.45 R38.2@2.85,76.45 v1(2.85,75.9) ; v1(3.2,78.5) 3.4,78.7 C3.1@3.85,78.7 3.85,79.15 4.45,79.75 U1.9@5.375,79.75 ; v1(3.875,86.406) 4.12,86.65 C2.1@4.4,86.65 4.4,86.05 4.675,85.775 4.675,83.925 4.85,83.75 U1.1@5.375,83.75 ; R45.2@5.85,74.8 v1(6.4,74.8) ; v1(6.2,86.2) 6.2,86.318 6.382,86.5 C5.1@6.7,86.5 6.7,86.1 6.75,86.05 U1.48@6.75,85.125 ; R6.2@11.7,69.7 v1(12.25,69.7) ; U1.24@12.25,76.875 12.25,75.8 12.3,75.75 C4.2@12.3,75.25 v1(12.85,75.25) ; R11.1@13.3,86.5 13.7,86.5 v1(13.95,86.25) ; U1.36@13.625,83.75 14.5,83.75 14.55,83.8 C6.1@15,83.8 15.5,83.8 v1(15.6,83.9)
  Top Layer w0.3: v1(10.65,73.65) 11.484,73.65 Q3.C@11.5,73.666 ; v1(19.8,67.1) 20.25,67.55 R56.2@20.25,69.119
  Top Layer w0.4: R50.2@20.081,77.25 v1(20.642,77.25)
  F2 w0.4: v1(20.642,77.25) v1@20.65,77.242
  F3 w0.3: 20.8,76.25 21.2,75.85 24,75.85 24.575,76.425
  F3 w0.4: v1(20.642,77.25) 20.642,76.408 20.8,76.25 ; V46.1@24,83.5 24.35,83.5 25.7,82.15 25.7,78.95 25.35,78.6 25.35,77.2 24.575,76.425
  Bottom Layer w0.4: V46.1@24,83.5 24.35,83.5 24.75,83.1 27.57,83.1 28.21,83.74 J6.3@28.21,85.285 J6.3@28.21,85.535
  other v1: 18.3,67.1 19.25,67.1 17,67.2
VDD_A: C38.2 C39.2 U6.14 | length 2
  Top Layer w0.25: U6.14@37.2,82.888 37.2,83.55 37.275,83.625 C38.2@37.275,84.125 C39.2@37.275,84.875
VDD_AM: C47.2 C48.2 U6.6 | length 2.8
  Top Layer w0.25: C48.2@37.2,76.25 C47.2@37.2,77 37.2,77.5 37.7,78 U6.6@37.7,78.862
VDD_D: C49.2 C50.2 U6.5 | length 2.9
  Top Layer w0.25: C50.2@36.55,76.25 C49.2@36.55,77 36.725,77.175 36.725,77.625 37.2,78.1 U6.5@37.2,78.862
VDD_DR: C45.2 C46.2 U6.8 | length 3.8
  Top Layer w0.25: U6.8@38.463,80.125 39.017,80.125 39.55,79.592 39.575,79.567 39.575,78.517 39.917,78.175 40.025,78.175 C45.2@40.075,78.125 C46.2@40.075,77.375
VDD_RF: C32.2 D2.K D3.K pad.2 pad.4 R14.2 R37.2 R58.2 U4.3 | length 17
  Top Layer w0.25: R37.2@41.231,74.7 pad.4@41.8,74.7 ; pad.4@41.801,74.699 pad.4@41.822,74.699
  Top Layer w0.3: R58.2@28.131,64.45 28.131,65.273 U4.3@28.2,65.342
  F3 w0.45: v1(34.7,64.45) 38.45,64.45 40.9,66.9 40.9,73.65 pad.4@41.95,74.7
VDD_STM32: C33.2 C40.2 C41.2 C42.1 C43.2 C51.2 R35.1 R36.2 U4.4 U4.5 U7.4 U7.20 V32.1 | length 9.6
  Top Layer w0.25: C40.2@27.3,73.219 27.3,72.85 27.605,72.545 28.055,72.545 C42.1@28.05,72.55 28.075,72.525 29.5,72.525 U7.20@29.525,72.5 ; U7.4@34.475,72 35.1,72 35.15,71.95 C43.2@35.5,71.95 35.676,71.95 36.176,72.45 C41.2@36.25,72.45 36.405,72.295 36.405,72.055 v1(36.25,71.9) ; R35.1@35.125,76.119 35.125,75.575 C51.2@35.325,75.375 35.325,74.835 35.33,74.83 v1(35.33,74.825) ; v1(37.2,74.05) 37.721,74.571 37.721,74.974 38.27,75.523 38.27,75.901 R36.2@38.619,76.25
  other v1: 29.72,68.51 30.39,68.5 28.65,72.5
XTI: C37.2 SB2.2 U6.19 X2.3 | length 5.5
  Top Layer w0.15: SB2.2@30.01,81.911 30.129,82.03 30.695,82.03 30.932,82.268 X2.3@31.125,82.075 31.125,81.985 31.813,81.297 32.91,81.297 33.375,81.761 C37.2@33.375,82.2 33.65,82.2 33.725,82.125 34.237,82.125
XTO: C44.2 SB3.2 U6.20 X2.1 | length 4.4
  Top Layer w0.15: SB3.2@30.921,79.48 30.931,79.49 C44.2@31.55,79.49 31.55,79.56 31.71,79.72 31.71,79.79 32.375,80.455 X2.1@32.375,80.525 32.375,80.575 32.726,80.926 33.032,80.926 33.731,81.625 34.237,81.625
pads on no net: J1.4 J2.6 J2.MEC J6.1 J6.2 J6.8 J6.9 J6.10 J6.11 J6.12 MIR1.1 MIR2.1 MIR3.1 P2.5 P2.7 U1.11 U1.14 U1.16 U1.19 U1.21 U1.22 U1.29 U1.31 U1.40 U1.41 U1.42 U1.43 U1.45 U1.46 U2.2 U4.6 U8.1 U8.2 U8.5
copper on no net:
  other v1: 80.104,74.986 81.404,74.986 82.704,74.985 66.946,75 68.246,75 80.754,75.986 82.054,75.986 83.354,75.985 66.296,76 67.596,76

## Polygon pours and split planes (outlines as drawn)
GND on Top Layer "REMPLISSAGE-GND-ST25R200" (solid, remove dead copper, pour order 62): 33.75,84.169 33.75,77.25 40.635,77.25 40.635,84.169
GND_50R on Top Layer "rempl3-gnd-fc" (solid, remove dead copper, pour order 58): 59.25,60.5 59.25,29.25 84,29.25 84,60.5
GND_FLEX_ANT on Top Layer "rempl2-gnd-fc" (solid, remove dead copper, pour order 57): 31.5,60.5 31.5,28 56.25,28 56.25,60.5
GND_C6_ANT on Top Layer "rempl4-gnd-fc" (solid, remove dead copper, pour order 56): 49.5,87.5 64.25,87.5 64.25,63.5 49.5,63.5
GND_HUB on Top Layer "rempl1-gnd-fc" (solid, remove dead copper, pour order 55): -1.5,26 28.5,26 28.5,60.5 -1.5,60.5 -1.5,58
GND on Top Layer "GND_L01_P027" (solid, remove dead copper, pour order 27): 11.95,65.9 11.65,65.6 11.65,64.9 13.6,64.9 13.9,65.2 15.8,65.2 15.8,65.8 14.25,65.8 14.15,65.9
GND on Top Layer "GND_L01_P033" (solid, remove dead copper, pour order 33): 8.25,69.3 10.35,69.3 10.35,71.15 8.25,71.15
GND_USB on Top Layer "GND_USB_L01_P032" (solid, remove dead copper, pour order 32): 7.9,70.9 7.65,71.15 7.65,74.05 6.35,74.05 6.35,70.95 5.3,69.9 4.9,69.9 4.9,69.3 7.9,69.3
NetC1_2 on Top Layer "NETC1_2_L01_P031" (solid, remove dead copper, pour order 31): 5.95,71.2 5.75,71.2 5.1,70.55 2.65,70.55 2.65,74.05 5.95,74.05
GND_USB on Top Layer "GND_USB_L01_P030" (solid, remove dead copper, pour order 30): 4.5,64.75 4.55,64.75 9.5,64.75 9.5,62.8 4.5,62.8
GND on Top Layer "GND_L01_P029" (solid, remove dead copper, pour order 29): 20.75,65.85 16.9,65.85 16.9,64.95 17.55,64.95 18.1,64.4 18.65,64.4 18.65,63.55 20.75,63.55
VCC_STLK on Top Layer "VCC_STLK_L01_P028" (solid, remove dead copper, pour order 28): 16.45,66.15 20.85,66.15 20.85,67.65 19.45,67.65 16.45,67.65
5V_USB_CHGR on Top Layer "tgr" (solid, remove dead copper, pour order 26): 15.65,67.15 15.65,67.8 13.05,67.8 12.4,67.15 10,67.15 10,64.8 11.45,64.8 11.45,65.9 11.7,66.15 15.65,66.15
NetC8_2 on Top Layer "NETC8_2_L01_P025" (solid, remove dead copper, pour order 25): 3.45,67.3 5.25,67.3 5.4,67.15 9.5,67.15 9.5,65 6.7,65 6.55,65.15 5.45,65.15 5.15,65.45 5.15,66.3 4.55,66.9 3.45,66.9
V_USB on Top Layer "V_USB_L01_P023" (solid, remove dead copper, pour order 23): 34.45,84.5 34.45,83.45 34.15,83.15 32.95,83.15 32.9,83.2 32.9,84.5
G0_VBUS on Top Layer "G0_VBUS_L01_P022" (solid, remove dead copper, pour order 22): 34.6,85.15 34.25,84.8 33,84.8 32.65,85.15 32.55,85.15 30.375,85.15 30.375,86 32.25,86 32.9,86.65 34.2,86.65 34.2,87.65 36.3,87.65 36.3,85.75 35.2,85.75
G0_GND_USB on Top Layer "G0_GND_USB_L01_P021" (solid, remove dead copper, pour order 21): 32.45,84.85 32.45,83.25 30.7,83.25 30.35,83.6 30.35,84.85
G0_GND_USB on Top Layer "G0_GND_USB_L01_P020" (solid, remove dead copper, pour order 20): 29.125,84.85 29.125,84 28.5,84 27.8,83.3 26.9,83.3 26.9,85 24.55,85 24.55,87.5 26.5,87.5 26.5,86.55 28.2,84.85 28.55,84.85
GND on Top Layer "GND_L01_P019" (solid, remove dead copper, pour order 19): 26.5,83 26.5,84.75 25.1,84.75 25.1,83
GND on Top Layer "GND_L01_P002" (solid, remove dead copper, pour order 2): 28.8,65.875 28.625,66.05 26,66.05 25.85,65.875 23.5,65.875 23.5,67.375 25.1,67.375 25.1,67.55 28.95,67.55 29.125,67.375 30.5,67.375 30.5,65.875
VDD_STM32 on Top Layer "VDD_STM32_L01_P000" (solid, remove dead copper, pour order 0): 28.8,67.75 28.5,68.05 27,68.05 27,69.5 30.675,69.5 30.675,67.75
VDD_RF on Top Layer "VDD_RF_L01_P001" (solid, remove dead copper, pour order 1): 28.9,65.5 28.7,65.7 28,65.7 28,65.525 27.975,65.5 27.975,64 28.35,63.625 35.35,63.625 35.35,66.125 33.975,66.125 33.637,65.812 30.912,65.812 30.6,65.5
GND_50R on F2 "GND_50R_L02_P042" (solid, remove dead copper, pour order 42): 59.25,60.5 59.25,29.25 84,29.25 84,60.5
GND_FLEX_ANT on F2 "GND_FLEX_ANT_L02_P041" (solid, remove dead copper, pour order 41): 31.5,60.5 31.5,28 56.25,28 56.25,60.5
GND_HUB on F2 "GND_HUB_L02_P040" (solid, remove dead copper, pour order 40): -1.5,26 28.5,26 28.5,60.5 -1.5,60.5 -1.5,58
G0_GND_USB on F2 "G0_GND_USB_L02_P038" (solid, remove dead copper, pour order 38): 24.5,85 24.5,88.75 36.3,88.75 36.3,85.75 35.2,85.75 34.25,84.8 32.65,84.8 32.65,83.55 32.35,83.25 30.7,83.25 30.35,83.6 30.35,85.1 29.15,85.1 29.15,84 28.5,84 27.8,83.3 26.9,83.3 26.9,85
GND_USB on F2 "GND_USB_L02_P003" (solid, remove dead copper, pour order 3): 7.65,74.05 7.65,71.15 7.9,70.9 7.9,67.15 9.5,67.15 9.5,63.5 -0.7,63.5 -0.7,74.05
GND on F2 "GND_L02_P018" (solid, remove dead copper, pour order 18): -1.25,74.35 7.75,74.35 7.9,74.2 7.9,71.3 8.15,71.05 8.15,67.45 9.8,67.45 9.8,63.5 21.5,63.5 21.5,66.75 24.5,66.75 24.5,63.5 48,63.5 48,87.5 37,87.5 37,85.5 35.4,85.5 34.5,84.6 32.9,84.6 32.9,83.35 32.55,83 30.6,83 30.15,83.45 30.15,84.85 29.35,84.85 29.35,83.75 28.7,83.75 28.05,83.1 26.55,83.1 26.55,84.75 24.5,84.75 24.5,84.25 21.5,84.25 21.5,87.5 -1.25,87.5
GND_C6_ANT on F2 "GND_C6_ANT_L02_P034" (solid, remove dead copper, pour order 34): 49.5,87.5 64.25,87.5 64.25,63.5 49.5,63.5
GND_50R on F3 "GND_50R_L03_P053" (solid, remove dead copper, pour order 53): 59.23,60.5 59.23,29.25 83.98,29.25 83.98,60.5
GND_HUB on F3 "GND_HUB_L03_P049" (solid, remove dead copper, pour order 49): -1.5,26 28.5,26 28.5,60.5 -1.5,60.5 -1.5,58
GND_FLEX_ANT on F3 "GND_FLEX_ANT_L03_P044" (solid, remove dead copper, pour order 44): 31.5,60.5 31.5,28 56.25,28 56.25,60.5
GND_C6_ANT on F3 "GND_C6_ANT_L03_P043" (solid, remove dead copper, pour order 43): 49.5,87.5 64.25,87.5 64.25,63.5 49.5,63.5
G0_GND_USB on F3 "G0_GND_USB_L03_P037" (solid, remove dead copper, pour order 37): 24.5,88.25 24.5,85 26.9,85 26.9,83.3 27.8,83.3 28.1,83.6 28.1,83.85 29.45,85.2 29.45,88.3
GND on F3 "GND_L03_P039" (solid, remove dead copper, pour order 39): 21.5,87.5 21.5,84.25 24.5,84.25 24.5,87.5 47.75,87.5 47.75,63.5 24.5,63.5 24.5,66.75 21.5,66.75 21.5,63.5 -0.8,63.5 -0.8,87.5
5V_USB_CHGR on F3 "5V_USB_CHGR_L03_P036" (solid, remove dead copper, pour order 36): 15.25,80.85 11.15,80.85 10.6,80.3 10.6,78.85 11.3,78.15 12.55,78.15 13.65,77.05 13.65,73.9 12,72.25 8.95,72.25 8.25,71.55 8.25,69.35 11.35,66.25 13.75,66.25 13.75,69 11.75,69 11.75,70.5 12,70.75 18.5,70.75 18.5,83 17.75,83.75 16.25,83.75 15.25,82.75
VCC_STLK on F3 "VCC_STLK_L03_P035" (solid, remove dead copper, pour order 35): 13.375,74.125 13.375,76.875 12.35,77.9 11.15,77.9 10.25,78.8 10.25,80.55 10.75,81.05 15,81.05 15,83 16,84 18,84 18.75,83.25 18.75,76.5 21.5,76.5 21.5,86.25 20.5,87.25 15.75,87.25 15.15,86.65 2.55,86.65 2.55,75.4 3.225,74.725 3.225,68.525 6.55,65.2 9.15,65.2 10.35,64 15.6,64 17.35,65.75 20.1,65.75 20.1,69.15 18.75,70.5 12.25,70.5 12,70.25 12,69.25 14,69.25 14,66 11.3,66 8,69.3 8,71.7 8.8,72.5 11.75,72.5
5V_USB_CHGR on F3 "5V_USB_CHGR_L03_P005" (solid, remove dead copper, pour order 5): 32.5,69.45 30.85,67.8 28.7,67.8 28,68.5 28,76 17.2,76 17.2,72.37 25.03,72.37 25.3,72.1 25.3,66.45 27.5,64.25 33.3,64.25 33.3,64.9 32.4,65.8 32.4,66.95 32.85,67.4 33.7,67.4 33.95,67.15 34.75,67.15 34.85,67.25 37.25,67.25 38.5,68.5 38.5,69.45
V_USB on F3 "V_USB_L03_P024" (solid, remove dead copper, pour order 24): 38.75,71.55 37.8,72.5 37.8,75.3 38.35,75.85 38.35,77.948 38.75,78.348 38.75,80.8 37.35,82.2 32.5,82.2 32.5,83.2 33.05,83.75 37.45,83.75 40.5,80.7 40.5,67.35 38,64.85 33.85,64.85 32.75,65.95 32.75,66.8 32.9,66.95 37.25,66.95 38.75,68.45
VDD_STM32 on F3 "VDD_STM32_L03_P004" (solid, remove dead copper, pour order 4): 37.6,75.25 37.6,72.4 38.5,71.5 38.5,69.75 32.25,69.75 30.625,68.125 28.875,68.125 28.25,68.75 28.25,83.7 30.95,86.4 36.65,86.4 37.75,87.5 40.45,87.5 40.45,84.75 39.8,84.1 32.95,84.1 32.3,83.45 32.3,74.25 34.5,74.25 35.5,75.25
G0_GND_USB on Bottom Layer "G0_GND_USB_L04_P061" (solid, remove dead copper, pour order 61): 24.5,85 24.5,88.75 36.3,88.75 36.3,85.75 35.2,85.75 34.25,84.8 32.65,84.8 32.65,83.55 32.35,83.25 30.7,83.25 30.35,83.6 30.35,85.1 29.15,85.1 29.15,84 28.5,84 27.8,83.3 26.9,83.3 26.9,85
GND on Bottom Layer "REMPL1-GND-FS" (solid, remove dead copper, pour order 60): -1.25,74.35 7.75,74.35 7.9,74.2 7.9,71.3 8.15,71.05 8.15,67.45 9.8,67.45 9.8,63.5 21.5,63.5 21.5,66.75 24.5,66.75 24.5,63.5 48,63.5 48,87.5 37,87.5 37,85.5 35.4,85.5 34.5,84.6 32.9,84.6 32.9,83.35 32.55,83 30.6,83 30.15,83.45 30.15,84.85 29.35,84.85 29.35,83.75 28.7,83.75 28.05,83.1 26.55,83.1 26.55,84.75 24.5,84.75 24.5,84.25 21.5,84.25 21.5,87.5 -1.25,87.5
GND_USB on Bottom Layer "REMPL2-GND-FS" (solid, remove dead copper, pour order 59): 7.65,74.05 7.65,71.15 7.9,70.9 7.9,67.15 9.5,67.15 9.5,63.5 -0.7,63.5 -0.7,74.05
GND_50R on Bottom Layer "GND_50R_L04_P054" (solid, remove dead copper, pour order 54): 59.23,60.5 59.23,29.25 83.98,29.25 83.98,60.5
GND_HUB on Bottom Layer "GND_HUB_L04_P050" (solid, remove dead copper, pour order 50): -1.5,26 28.5,26 28.5,60.5 -1.5,60.5 -1.5,58
GND_FLEX_ANT on Bottom Layer "GND_FLEX_ANT_L04_P047" (solid, remove dead copper, pour order 47): 31.5,60.5 31.5,28 56.25,28 56.25,60.5
GND_C6_ANT on Bottom Layer "GND_C6_ANT_L04_P046" (solid, remove dead copper, pour order 46): 49.5,87.5 64.25,87.5 64.25,63.5 49.5,63.5

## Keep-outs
F3:
  region: 20.95,67.9 20.95,68.75 20.9,68.75 20.9,67.9
  region: 21,69.8 21,70.5 20.9,70.5 20.9,69.8
  region: 20.95,71.5 20.95,72.35 20.9,72.35 20.9,71.5
  region: 25.3,81.1 25.3,81.15 24.45,81.15 24.45,81.1
Bottom Layer:
  region: 7.2,79.5 7.2,80.25 6.95,80.25 6.95,79.5
  region: 17.05,72.1 17.05,72.2 15.95,72.2 15.95,72.1
  region: 46.55,80.95 46.55,81.1 45.5,81.1 45.5,80.95
  region: 34.6,68.432 34.6,68.7 32.555,68.7 32.555,68.432
  region: 38.15,73.35 38.15,76.25 38.1,76.25 38.1,73.35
